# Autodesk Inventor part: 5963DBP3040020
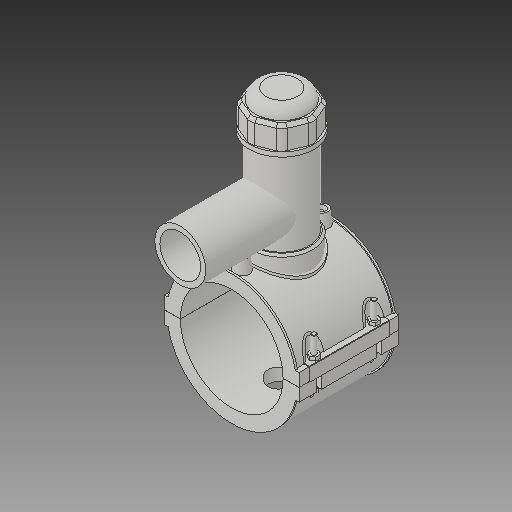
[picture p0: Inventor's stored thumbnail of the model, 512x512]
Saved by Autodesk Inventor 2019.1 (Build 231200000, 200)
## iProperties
Created: 2017-07
Part Number: 5963DBP3040020
Material: Generic
Description: PLASSON TAPPING SADDLE 4''DIPS x 2''IPS
Document SubType Name: Modeling
Designer: KIM
Density: 1 g/cm^3
Appearance: Default
Author: KIM
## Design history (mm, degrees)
derived "5963DBP_5963BUP.ipt"
feature "Solid1::5963DBP_5963BUP.ipt"
feature "Solid2::5963DBP_5963BUP.ipt"
feature "Solid3::5963DBP_5963BUP.ipt"
tag "TaggingFeature1"
body "Solid1"
body "Solid2"
body "Solid3"
other parameters: "d0" = 121.3, "d2" = 159.004, "d3" = 30.325, "d4" = 118.11, "d5" = 0, "d6" = 0.1, "d8" = 0, "d19" = 6, "d20" = 6, "d21" = 70.866, "d23" = 0, "d24" = 35.433, "d26" = 0, "d27" = 3, "d28" = 3, "d29" = 3, "d30" = 40.43333, "d31" = 6, "d32" = 0, "d33" = 0, "d34" = 0.6, "d40" = 78.21424, "d41" = 76.419, "d43" = 0, "d45" = 0, "d47" = 146.072, "d70" = 15, "d72" = 0, "d73" = 6, "d75" = 5, "d76" = 0, "d77" = 6.065, "d78" = 90.65, "d79" = 15, "d80" = 47.244, "d82" = 5 deg, "d84" = 4, "d85" = 14, "d86" = 0, "d87" = 3, "d88" = 0, "d89" = 1, "d90" = 1, "d91" = 94.488, "d92" = 0, "d93" = 0.5, "d94" = 63.84211, "d96" = 153.42024, "d97" = 2.3622, "d98" = 0, "d120" = 140 deg, "d121" = 24.228, "d122" = 20 deg, "d123" = 300.824, "d124" = 90.2472, "d126" = 0, "d143" = 124.939, "d145" = 22.39385, "d149" = 1.8195, "d150" = 24.63323, "d153" = 118.11, "d154" = 0, "d156" = 75.206, "d157" = 160 deg, "d159" = 5.8224, "d161" = 1.8195, "d162" = 70.866, "d163" = 0, "d164" = 60.65, "d167" = 12.13, "d168" = 73.37171, "d170" = 3.4335, "d172" = 0, "d173" = 1, "d175" = 60.65, "d176" = 20 deg, "d177" = 8.491, "d178" = 29.112, "d180" = 0, "d183" = 11.6448, "d184" = 6.7928, "d185" = 38.38575, "d186" = 38.38575, "d187" = 75.206, "d188" = 8.7336, "d189" = 8.491, "d190" = 0, "d191" = 112.809, "d193" = 7.3248, "d194" = 4.13385, "d195" = 90 deg, "d197" = 0, "d199" = 0, "d200" = 14.556, "d202" = 0, "d203" = 177.038, "d204" = 72.59805, "d205" = 53.4933, "d206" = 64.95615, "d207" = 132.7785, "d208" = 138.08964, "d209" = 164.64534, "d210" = 65.72034, "d211" = 76.419, "d212" = 61.1352, "d213" = 31.4766, "d216" = 0, "d217" = 12.13, "d218" = 12.13, "d219" = 2.426, "d222" = 121.3, "d224" = 0, "d225" = 65.024, "d226" = 60.1, "d227" = 48.08, "d228" = 119.888, "d230" = 3.639, "d_" = 121.3, "B_" = 159.004, "L_" = 118.11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
